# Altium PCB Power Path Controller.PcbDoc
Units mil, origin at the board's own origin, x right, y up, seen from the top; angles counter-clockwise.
Board outline 1945 x 1990 mil, 2 copper layers (Top Layer, Bottom Layer); 25 components, 17 nets, 53 pads, 3 vias.
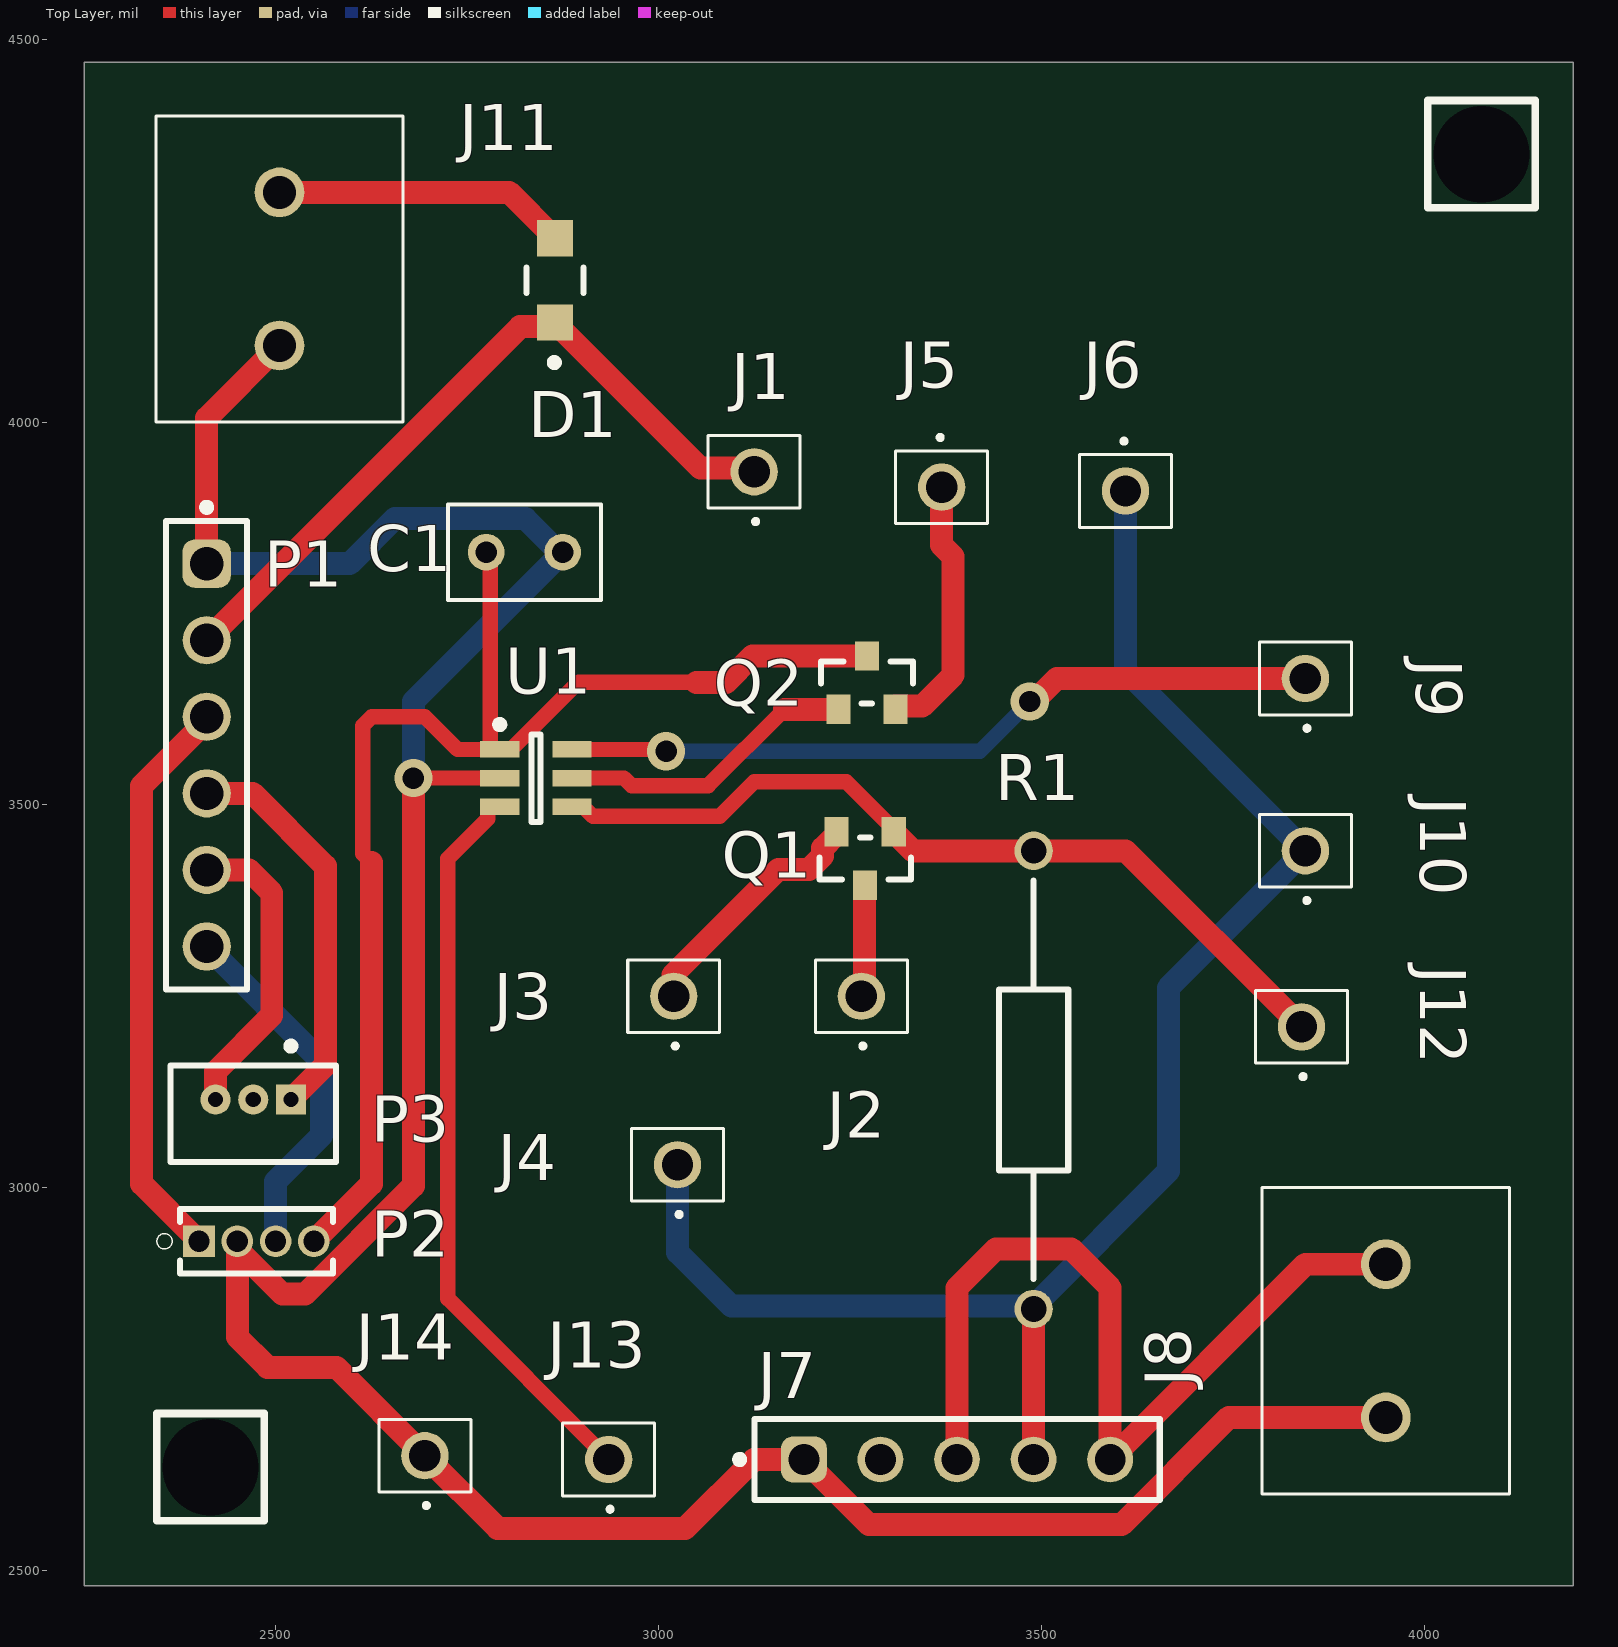
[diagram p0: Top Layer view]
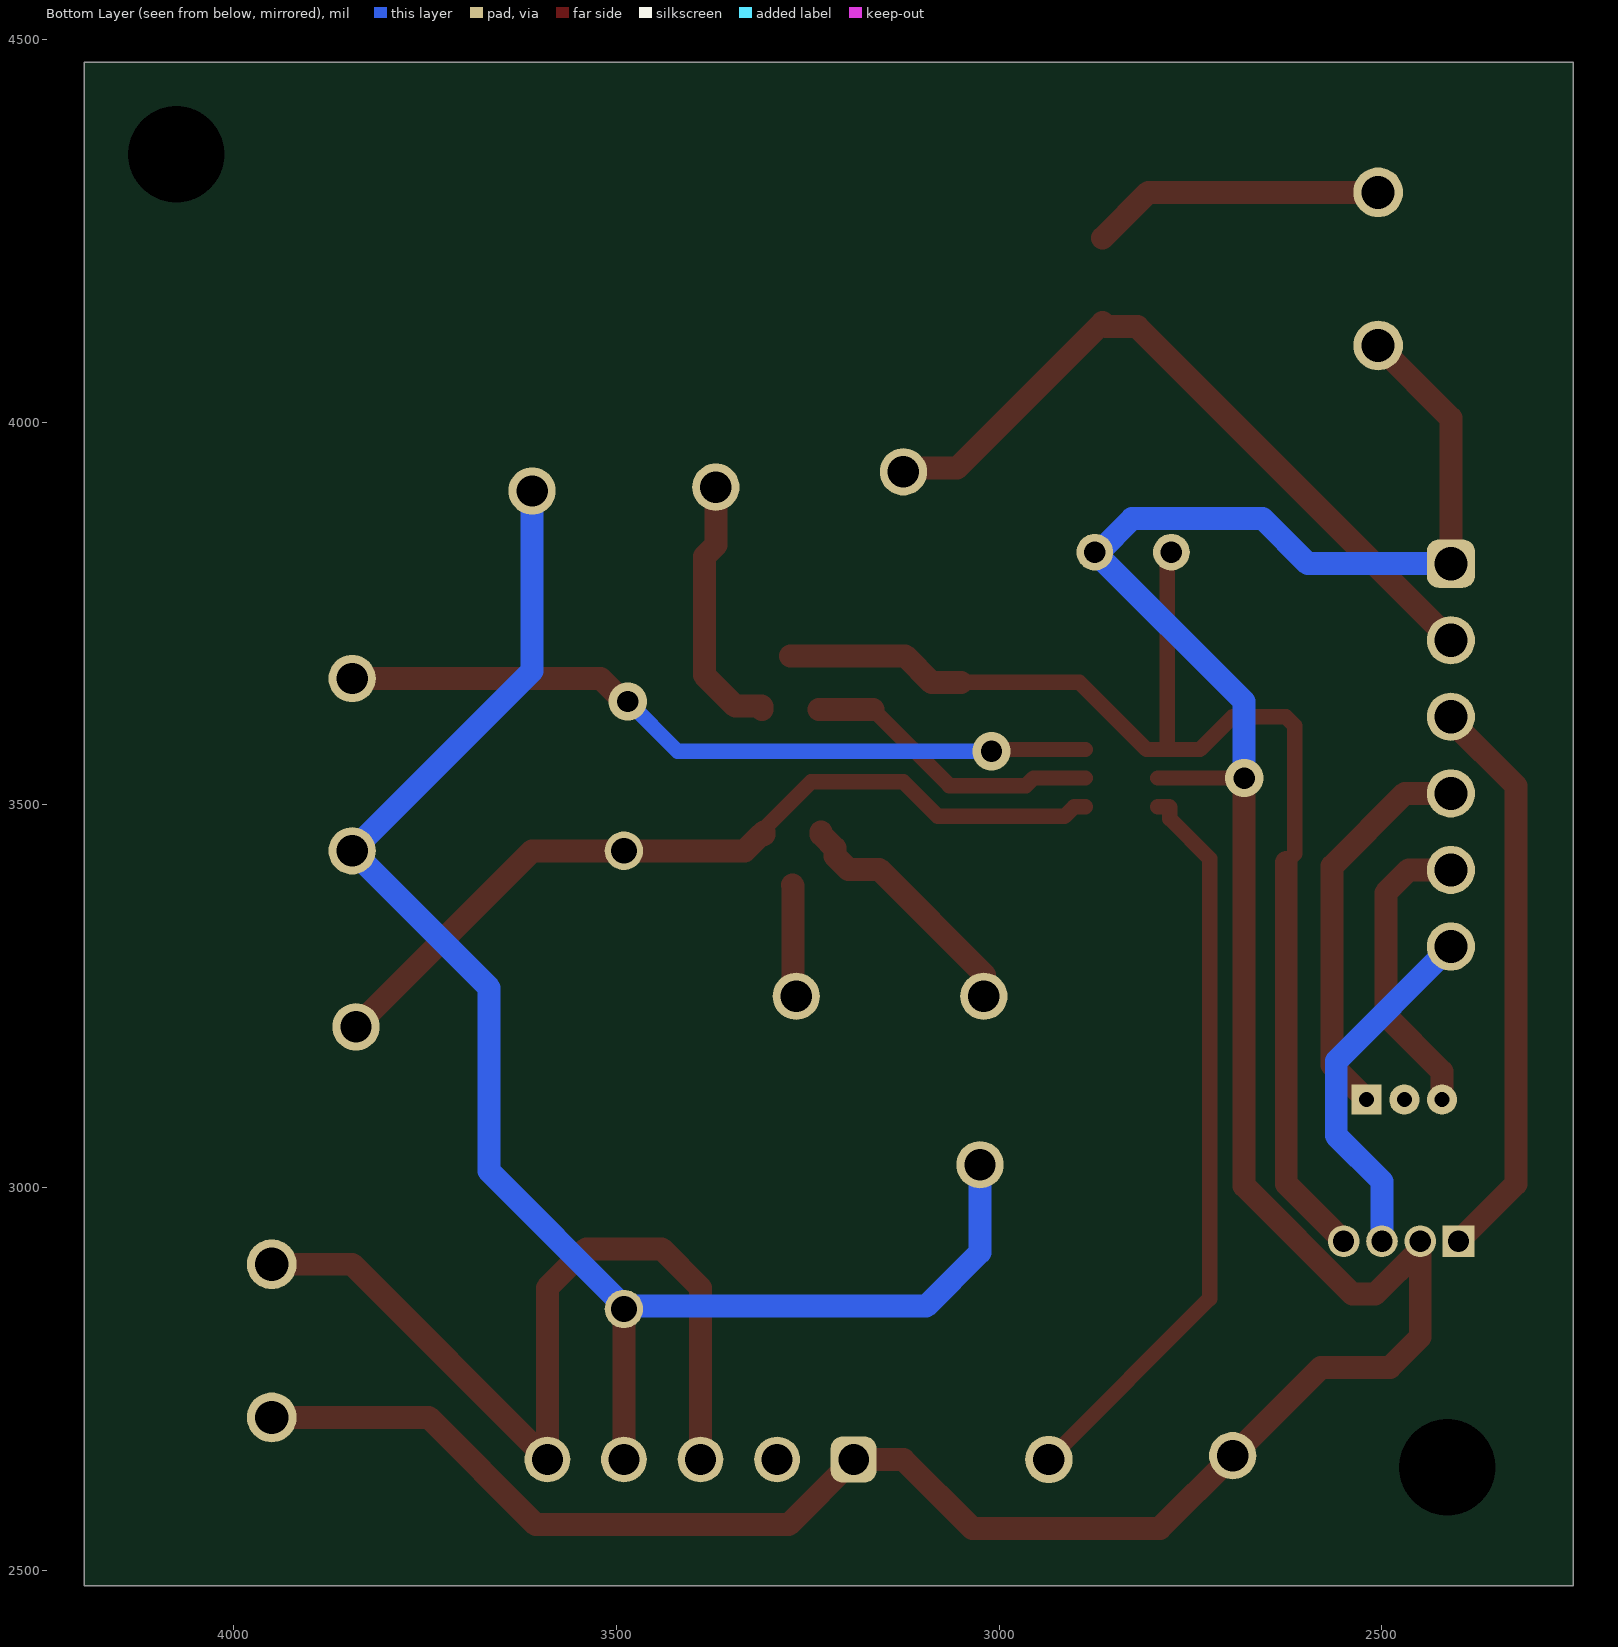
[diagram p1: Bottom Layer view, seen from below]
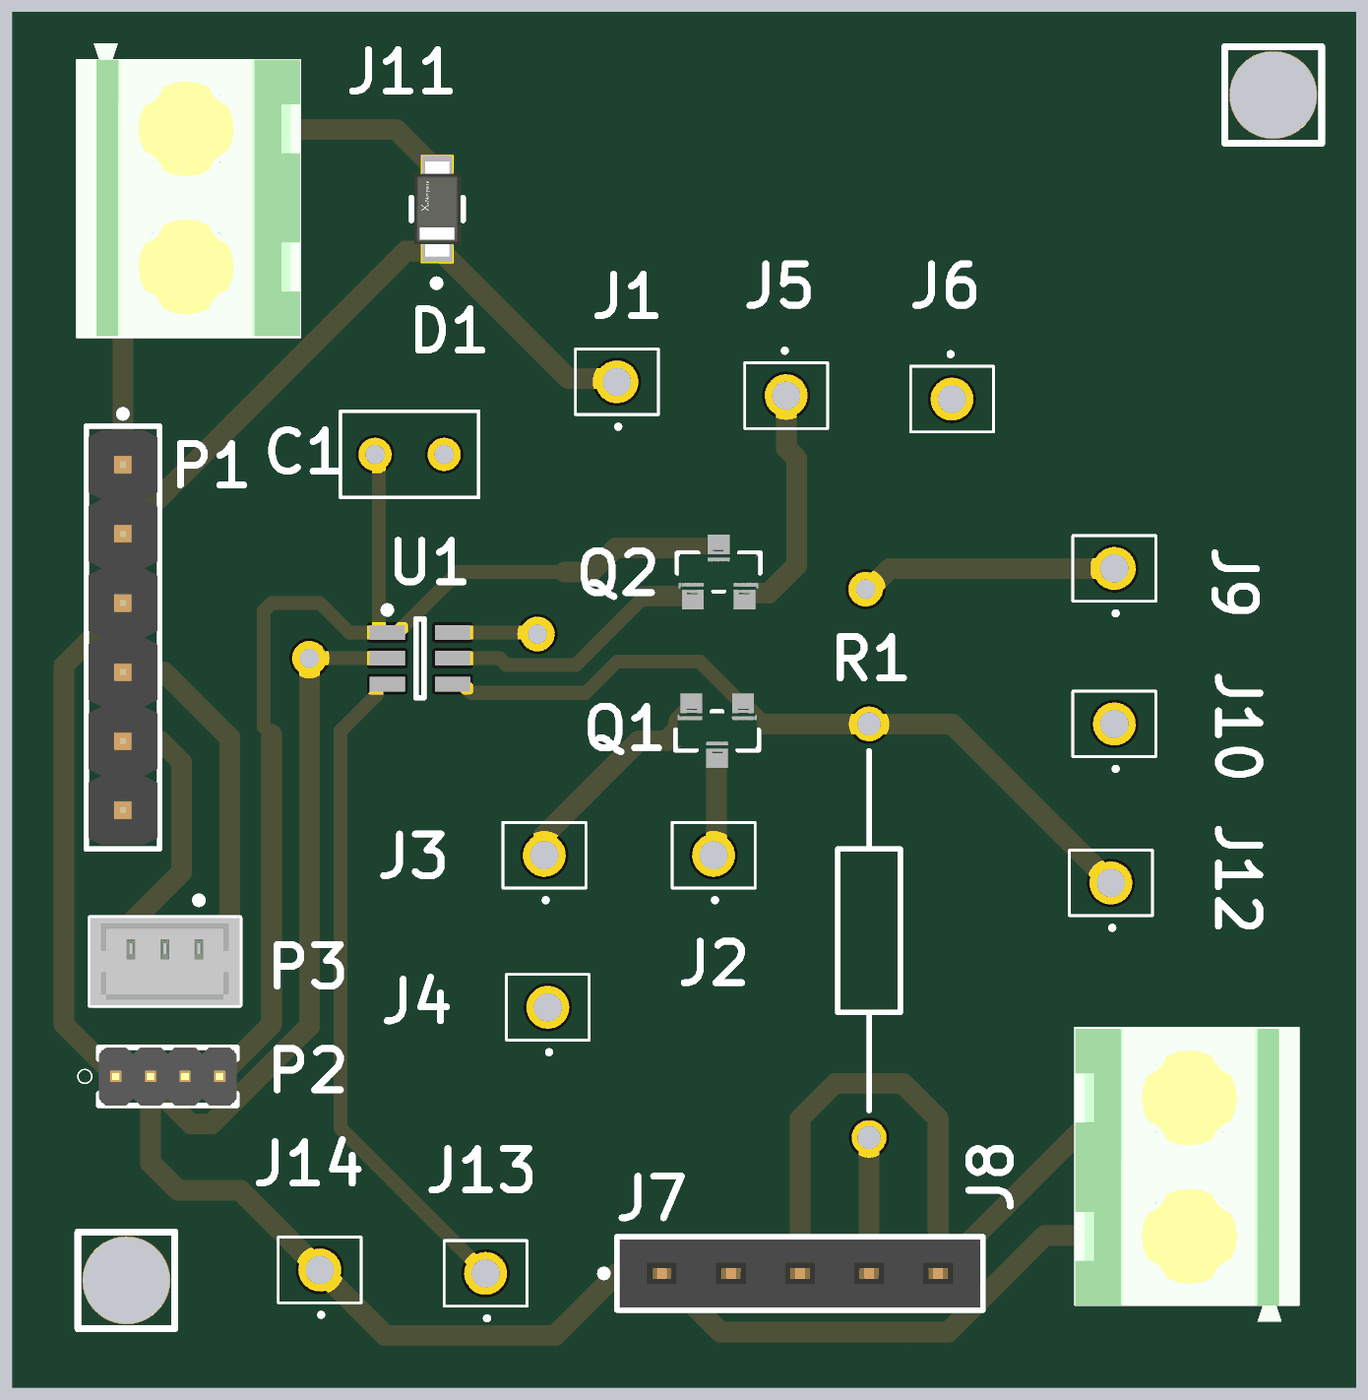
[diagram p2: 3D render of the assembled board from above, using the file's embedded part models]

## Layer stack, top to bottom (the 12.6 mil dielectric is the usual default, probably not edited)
Top Solder: solder mask 0.4, Solder Resist, Dk 3.5
Top Layer: signal copper 1.4
Dielectric 1: dielectric 12.6, FR-4, Dk 4.8
Bottom Layer: signal copper 1.4
Bottom Solder: solder mask 0.4, Solder Resist, Dk 3.5

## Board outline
2250,2480 4195,2480 4195,4470 2250,4470

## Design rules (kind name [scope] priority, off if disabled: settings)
Clearance [All] p1: gap=5 ignorepadtopadclearanceinfootprint=FALSE
PolygonConnect [All] p1: connectstyle=Relief reliefconductorwidth=10 reliefentries=4 polygonreliefangle="90 Angle" airgapwidth=10
RoutingVias [All] p1: holewidth=28 width=50 viastyle="Through Hole" minholewidth=28 minwidth=50 maxholewidth=28 maxwidth=50
SolderMaskExpansion [All] p1: expansion=4 istentingtop=FALSE
SupplyNets "Schematic Supply Nets_1" [InNet('GND')] p1: voltage=0.000
Width [All] p1: maxlimit=30 minlimit=10 preferedwidth=20
30 further rules are at their usual default settings.

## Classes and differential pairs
component class "Power Path Controller": C1 D1 J1 J2 J3 J4 J5 J6 J7 J8 J9 J10 J11 J12 J13 J14 P1 P2 P3 Q1 Q2 R1 U1

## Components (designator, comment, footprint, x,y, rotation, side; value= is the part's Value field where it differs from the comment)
C1 "10uF" CAPRR254W50L508T317H508 2825,3830 r0 top
D1 "PMEG6020AELRX" FP-SOD123W-MFG 2865,4185 r90 top
J1 "SSW-101-01-T-S" SSW-101-XX-YYY-S 3125,3935 r0 top
J2 "SSW-101-01-T-S" SSW-101-XX-YYY-S 3265,3250 r0 top
J3 "SSW-101-01-T-S" SSW-101-XX-YYY-S 3020,3250 r0 top
J4 "SSW-101-01-T-S" SSW-101-XX-YYY-S 3025,3030 r0 top
J5 "SSW-101-01-T-S" SSW-101-XX-YYY-S 3370,3915 r180 top
J6 "SSW-101-01-T-S" SSW-101-XX-YYY-S 3610,3910 r180 top
J7 "Power Pushbutton" 61300511821 3390,2645 r0 top
J8 "282837-2" 2828372 3950,2900 r270 top
J9 "SSW-101-01-T-S" SSW-101-XX-YYY-S 3845,3665 r0 top
J10 "SSW-101-01-T-S" SSW-101-XX-YYY-S 3845,3440 r0 top
J11 "282837-2" 2828372 2505,4100 r90 top
J12 "Status" SSW-101-XX-YYY-S 3840,3210 r0 top
J13 "SSW-101-01-T-S" SSW-101-XX-YYY-S 2935,2645 r0 top
J14 "SSW-101-01-T-S" SSW-101-XX-YYY-S 2695,2650 r0 top
P1 "Dual Protection TP4056" 61300611121 2410,3565 r270 top
P2 "GRPB041VWVN-RC" HDRV4W40P127_1X4_508X214X400P 2475,2930 r0 top
P3 "530470310" MOLX-530470310_V 2470.79,3115 r0 top
Q1 "IRLML6402TRPBF" FP-Micro3-MFG 3270,3430 r270 top
Q2 "IRLML6402TRPBF" FP-Micro3-MFG 3272.4,3659.68 r90 top
R1 "470k" RESAD1520W63L600D230 3490,3440 r270 top
U1 "LTC4412HVIS6#TRMPBF" LT-S6-6-TSOT-23_N 2840,3535 r0 top
? "Mounting Hole" MTHNP3P2MM 4075,4350 r0 top
? "Mounting Hole" MTHNP3P2MM 2415,2635 r0 top

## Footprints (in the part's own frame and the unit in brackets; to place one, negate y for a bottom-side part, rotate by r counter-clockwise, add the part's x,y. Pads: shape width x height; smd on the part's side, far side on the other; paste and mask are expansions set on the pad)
2828372 [mm]
  round 1.65 hole 1.1: 1(0,0) 2(5.08,0)
  silkscreen extent -2.54,-4.1 7.62,4.1, body extent -2.51,-4.11 8.25,4.09, height 9.84
61300511821 [mm] "Socket Header, Pitch 2.54 mm, THT, Vertical, single row, 5p"
  rrect50% 1.52x1.52 hole 1.02: 1(-5.08,0)
  round 1.52 hole 1.02: 2(-2.54,0) 3(0,0) 4(2.54,0) 5(5.08,0)
  silkscreen extent -7.33,-1.35 6.73,1.35, body extent -6.6,-1.25 6.6,1.25, height 8.55
61300611121 [mm] "Pin Header, pitch 2.54 mm, THT, Vertical, single row, 6p"
  rrect50% 1.6x1.6 hole 1.1: 1(-6.35,0)
  round 1.6 hole 1.1: 2(-3.81,0) 3(-1.27,0) 4(1.27,0) 5(3.81,0) 6(6.35,0)
  silkscreen extent -8.34,-1.35 7.77,1.35, body extent -7.62,-1.27 7.62,1.27, height 8.57
CAPRR254W50L508T317H508 [mm]
  round 1.218 hole 0.71: 1(-1.27,0) 2(1.27,0)
  silkscreen extent -2.54,-1.59 2.54,1.59
FP-Micro3-MFG [mm]
  rect 0.972x0.802 smd paste+0 mask+0: 1(-0.885,0.95) 2(-0.885,-0.95) 3(0.885,0)
  silkscreen extent -0.7,-1.52 0.7,1.52, body extent -1.47,-1.87 1.47,1.87, height 0.25
FP-SOD123W-MFG [mm]
  rect 1.2x1.2 smd paste-1000 mask+0: 1(-1.4,0) 2(1.4,0)
  silkscreen extent -2.85,-0.95 0.43,0.95, body extent -2.2,-1.05 2.2,1.05, height 0.25
HDRV4W40P127_1X4_508X214X400P [mm]
  rect 1.05x1.05 / inner round 1.05 / far side rect 1.05x1.05 hole 0.7: 1(-1.905,0)
  round 1.05 hole 0.7: 2(-0.635,0) 3(0.635,0) 4(1.905,0)
  silkscreen extent -3.3,-1.07 2.54,1.07, body extent -2.54,-1.07 2.54,1.07, height 3.99
LT-S6-6-TSOT-23_N [mm] "SOT23, 6-Leads, Body 2.9x1.75mm, Pitch 0.95mm, IPC Medium Density"
  rect 1.3x0.55 smd: 1(-1.2,0.95) 2(-1.2,0) 3(-1.2,-0.95) 4(1.2,-0.95) 5(1.2,0) 6(1.2,0.95)
  silkscreen extent -1.32,-1.45 0.15,1.9, body extent -0.87,-1.45 0.87,1.45, height 1
MOLX-530470310_V [mm] "THD, 3-Leads, Body 5.5x3.2mm, Pitch 1.25mm"
  rect 1x1 hole 0.5: 1(1.25,0)
  round 1 hole 0.5: 2(0,0) 3(-1.25,0)
  silkscreen extent -2.75,-2.07 2.75,1.9, body extent -2.75,-2.07 2.75,1.13, height 4.18
MTHNP3P2MM [mm] "Mounting Hole Non-Plated 3.2mm"
  round 0 hole 3.2: ""(0,0)
  silkscreen extent -1.78,-1.78 1.78,1.78
RESAD1520W63L600D230 [mm]
  round 1.275 hole 0.85: 1(0,0) 2(15.2,0)
  silkscreen extent 0.99,-1.15 14.21,1.15
SSW-101-XX-YYY-S [mm]
  round 1.57 hole 1.04: 1(0,0)
  silkscreen extent -1.53,-1.7 1.53,1.2

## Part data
C1: library part FA16X7R1E106KRU00, "10 ÂµF Â±10% 25V Ceramic Capacitor X7R Radial", Package="Radial TDK"
D1: library part CMP-14398-000040-1, "DIODE SCHOTTKY 60V 2A CFP3"
J1 J2 J3 J4 J5 J6 J9 J10 J13 J14: "Connector", Manufacturer_Name=SAMTEC, Mouser Part Number=200-SSW10101TS
J7: library part CMP-1502-01320-3, "61300511821", Contact Resistance=20mΩ, Current Rating=3A, Operating Supply Voltage=250V
J8 J11: "Connector", Manufacturer_Name="TE Connectivity", Mouser Part Number=571-2828372
J12: library part SSW-101-01-T-S, "Connector SSW-101-01-T-S", Manufacturer_Name=SAMTEC, Mouser Part Number=200-SSW10101TS
P1: library part CMP-1502-01070-3, Color=Black, Contact Resistance=20mΩ, Current Rating=3A, Max Operating Temperature=105°C, Min Operating Temperature=-40°C, Operating Supply Voltage=250V
P2: library part 61300411821, "Connector", Manufacturer_Name="Wurth Elektronik", Mouser Part Number=710-61300411821
P3: library part CMP-2000-05465-1, "Male Header, Pitch 1.25 mm, 1 x 3 Position, Height 4.2 mm, Tail Length 2.3 mm, -40 to 85 degC, RoHS, Tray", Manufacturer=Molex, Package Description="Male Header, Pitch 1.25 mm, 1 x 3 Position, Height 4.2 mm, Tail Length 2.3 mm"
Q1 Q2: library part CMP-32901-000130-1, "MOSFET P-CH 20V 3.7A SOT-23", Continuous Drain Current=-3.7A, Drain To Source Breakdown Voltage=-20V, Drain To Source Resistance=0.05Ω, Gate To Source Voltage=12V, Input Capacitace At Vds="633pF @ -10V", Manufacturer=Infineon, Max Forward Diode Voltage=-1.2V, Max Junction Temp=+150°C, Package=Micro3, Power Dissipation=1.3W, Pulse Drain Current=-22A, Temperature="-55°C to +150°C", Temperature Range Low=-55°C
R1: library part CF14JT470K, "Resistor CF14JT470K", Manufacturer_Name="Stackpole Electronics", Mouser Part Number=708-CF14JT470K
U1: library part CMP-0479-00434-1, "Low Loss PowerPath(TM) Controller, 2.5 to 36 V Vin, 6-pin SOT23 (S6-6), -40 to 125 degC, Pb-Free, Mini Tape and Reel", Manufacturer="Linear Technology"

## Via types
v1: diameter 50, hole 28, Top Layer to Bottom Layer, 3 vias

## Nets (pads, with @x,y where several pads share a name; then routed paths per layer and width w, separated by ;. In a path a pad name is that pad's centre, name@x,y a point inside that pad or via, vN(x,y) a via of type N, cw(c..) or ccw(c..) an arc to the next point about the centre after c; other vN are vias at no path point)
GND: C1.2 J7.1 J8.2 J11.1 J14.1 P1.1 P2.2 U1.2 | length 4035
  Top Layer w20: v1(2680,3535) U1.2
  Top Layer w30: P1.1 2410,4005 J11.1 ; v1(2680,3535) 2680,3002.49 2538.68,2861.17 2508.83,2861.17 2452.17,2917.83 2452.17,2927.83 P2.2 2450,2917.6 2450,2805 2489.54,2765.46 2579.54,2765.46 J14.1 2790,2555 3035,2555 3125,2645 J7.1 3275,2560 3605,2560 3745,2700 J8.2
  Bottom Layer w30: P1.1 2596.81,3815 2655.79,3873.98 2826.17,3873.98 2870.14,3830 C1.2 2680,3635 v1(2680,3535)
NetC1_1: C1.1 P2.4 Q2.3 U1.1 | length 1700.4
  Top Layer w20: 2625,3425 2613.71,3436.29 2613.71,3603.28 2625.43,3615 2695,3615 2737.6,3572.4 U1.1@2780.35,3572.4 ; C1.1 2780.35,3824.65 2780.35,3573.23 2781.18,3572.4 U1.1 2807.52,3572.4 2895.12,3660 3050,3660
  Top Layer w30: P2.4 2625,3005 2625,3425 ; 3050,3660 3050.32,3659.68 3088.01,3659.68 3122.85,3694.53 Q2.3
NetD1_1: D1.1 J1.1 P1.2 | length 967.6
  Top Layer w30: P1.2 2819.5,4124.5 2859.62,4124.5 D1.1 3054.88,3940 3120,3940 J1.1
NetD1_2: D1.2 J11.2 | length 384.8
  Top Layer w30: J11.2 2805.12,4300 D1.2
NetJ2_1: J2.1 Q1.3 | length 147.2
  Top Layer w30: J2.1 3269.21,3254.21 3269.21,3394.37 Q1.3
NetJ3_1: J3.1 Q1.2 | length 327.3
  Top Layer w30: J3.1 3018.91,3251.09 3018.91,3277.81 3156.81,3415.71 3196.97,3415.71 3214.54,3433.28 3214.54,3443.44 3232.6,3461.5 Q1.2
NetJ4_1: J4.1 J6.1 J7.4 J10.1 R1.2 | length 2118
  Top Layer w30: J7.4 R1.2@3490,2845.39
  Bottom Layer w30: J4.1 3025,2915.59 3095.4,2845.2 3489.8,2845.2 3490,2845.39 3666.11,3021.5 3666.11,3261.11 J10.1 3610,3675 J6.1
NetJ5_1: J5.1 Q2.2 | length 347.4
  Top Layer w30: Q2.2 3309.8,3628.19 3310.59,3628.98 3344.56,3628.98 3385,3669.42 3385,3824.09 3370,3839.09 J5.1
NetJ7_3: J7.3 J7.5 J8.1 | length 1156
  Top Layer w30: J7.3 3390,2869.12 3440.88,2920 3539.12,2920 3590,2869.12 J7.5 3845,2900 J8.1
NetJ9_1: J9.1 U1.6 | length 998.1
  Top Layer w20: U1.6 3007.6,3572.4 v1(3010,3570)
  Top Layer w30: v1(3485,3635) 3490.41,3635 3520.41,3665 J9.1
  Bottom Layer w20: v1(3010,3570) 3420,3570 v1(3485,3635)
NetJ12_1: J12.1 Q1.1 R1.1 U1.4 | length 1117.9
  Top Layer w20: U1.4 2902.01,3497.6 2902.83,3496.77 2902.83,3496.72 2914.55,3485 3080,3485 3125,3530 3245.59,3530 3310.81,3464.78 Q1.1@3310.81,3461.44
  Top Layer w30: Q1.1 3307.4,3461.5 3308.19,3460.71 3311.54,3460.71 3332.24,3440 3610,3440 J12.1
NetJ13_1: J13.1 U1.3 | length 976.3
  Top Layer w20: U1.3 2777.99,3497.6 2777.17,3496.77 2777.17,3482.01 2725,3429.84 2725,2855 J13.1
NetP1_3: P1.3 P2.1 | length 751.3
  Top Layer w30: P2.1 2325,3005 2325,3524.81 2410,3609.81 P1.3
NetP1_4: P1.4 P3.1 | length 518
  Top Layer w30: P1.4 2470,3515 2565,3420 2565,3160 P3.1
NetP1_5: P1.5 P3.3 | length 397.8
  Top Layer w30: P1.5 2465,3415 2495,3385 2495,3225 2421.57,3151.57 P3.3
NetP1_6: P1.6 P2.3 | length 471.7
  Bottom Layer w30: P1.6 2559.69,3165.31 2559.69,3067.86 2500,3008.18 P2.3
NetQ2_1: Q2.1 U1.5 | length 393.3
  Top Layer w20: U1.5 2955,3535 2965,3525 3065,3525 3164.84,3624.84
  Top Layer w30: 3164.84,3624.84 Q2.1
pads on no net: ?. J7.2 P3.2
